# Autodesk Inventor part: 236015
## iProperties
Created: 2006-07
Part Number: 236015
Material: St vz
Description: Scheibe
Vendor: Autodesk Inc.
Document SubType Name: Modeling
Standard: DIN 125
Designer: I.Baliuc
Standards Organization: DIN
Language: de-DE
Size Designation: A 13
Categories: <MemberInstance Version="R10.0.0"><Categories><Category DisplayName="Schrauben" InternalName="e4da775c-781d-43d5-af7c-5136215cf5a6" Mnemonic="FSTN"><Category Di
Density: 7.85 g/cm^3
Mass: 6.27327 g
Surface Area: 9.29911 cm^2
Volume: 0.799143 cm^3
Abmessung: A12
Author: T.Messerschmitt
Comments: DIN 125 - A 13
Revision Number: 236015
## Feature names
1. Körper [Extrusion]
